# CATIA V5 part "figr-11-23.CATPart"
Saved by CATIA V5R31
Part number: Part1
Bounding box of the stored display mesh (mm): x -89.703 to 75.958, y -127.286 to 108.862, z -26.487 to 19.815
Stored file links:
  D:\PROJECTS\Project 2021\US EDITION\CATIA V5 6R 2021\Resources\Part Files\c11_catia_v5_6r2021_prt\figr-11-23.CATPart
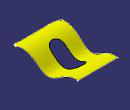
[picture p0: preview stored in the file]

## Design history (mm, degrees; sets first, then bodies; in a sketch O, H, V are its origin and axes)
Set1
  Extrude1: Element1 Sketch3, Lim1 86, Lim2 94, Direction yz-plane
  Sketch1 on xy-plane, origin (0, 0, 0), H (1, 0, 0), V (0, 1, 0)
    line L1 (64.3059, 108.8616) -> (75.9293, -106.0218)
    arc A1 centre (55.7837, -107.1115) radius 20.175 from (75.9293, -106.0218) to (55.7837, -127.2865) cw
    line L2 (55.7837, -127.2865) -> (-64.7868, -127.2865)
    arc A2 centre (-64.7868, -102.3613) radius 24.9252 from (-64.7868, -127.2865) to (-89.6873, -101.2501) cw
    line L3 (-89.6873, -101.2501) -> (-80.3115, 108.8616)
    line L4 (-80.3115, 108.8616) -> (64.3059, 108.8616)
    tangency: A1 L1, A2 L2, A2 L3, A1 L2
    horizontal: L2 H, L4 H
  Extrude2: Element1 Sketch1, Lim1 86, Lim2 94, Direction xy-plane
  Split1: ToCut Extrude1, Cutting Extrude2
  Sketch2 on xy-plane, origin (0, 0, 0), H (1, 0, 0), V (0, 1, 0)
    construction line L1 (-11.3849, 28.4134) -> (-11.3849, -36.9379)
    line L2 (12.8382, 28.4134) -> (12.8382, -36.9379)
    line L3 (-35.608, -36.9379) -> (-35.608, 28.4134)
    arc A1 centre (-11.3849, -36.9379) radius 24.2231 from (12.8382, -36.9379) to (-35.608, -36.9379) cw
    arc A2 centre (-11.3849, 28.4134) radius 24.2231 from (-35.608, 28.4134) to (12.8382, 28.4134) cw
    vertical: L1 V
    tangency: A1 L2, A2 L2, A1 L3, A2 L3
    parallelism: L1 L2
  Extrude3: Element1 Sketch2, Lim1 86, Lim2 94, Direction xy-plane
  Split2: ToCut Split1, Cutting Extrude3
  Boundary1: Boundary edge of Split2, Support Split2
Body1 (main body)
  Sketch3 on yz-plane, origin (0, 0, 0), H (0, 1, 0), V (0, 0, 1)
    spline S1 through (-130.9721, 0) (-85.5087, 19.8151) (-38.0512, 0) (0, -25.6483) (60.0541, -1.7202) (134.7951, -4.3868)
    point P1 (-130.9721, 0)
    point P2 (-38.0512, 0)
    point P3 (0, -25.6483)
    coincidence: P1 H, P2 H, P3 V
